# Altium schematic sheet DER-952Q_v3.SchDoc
size A3; Organization: Power Integrations Switzerland GmbH; SheetNumber: 1; SheetTotal: 1; PageSetup: Record=PageOptions¦CenterHorizontal=True¦CenterVertical=True¦PrintScale=1.00¦XCorrection=1.00¦YCorrection=1.00¦PrintKind=0¦BorderSize=5000000¦LeftOffset=0¦BottomOffset=0¦Orientation=2¦PaperLength=4200¦PaperWidth=2970¦Scale=100¦PaperSource=7¦PrintQuality=600¦MediaType=1¦DitherType=10¦PaperKind=A3¦PrintScaleMode=1
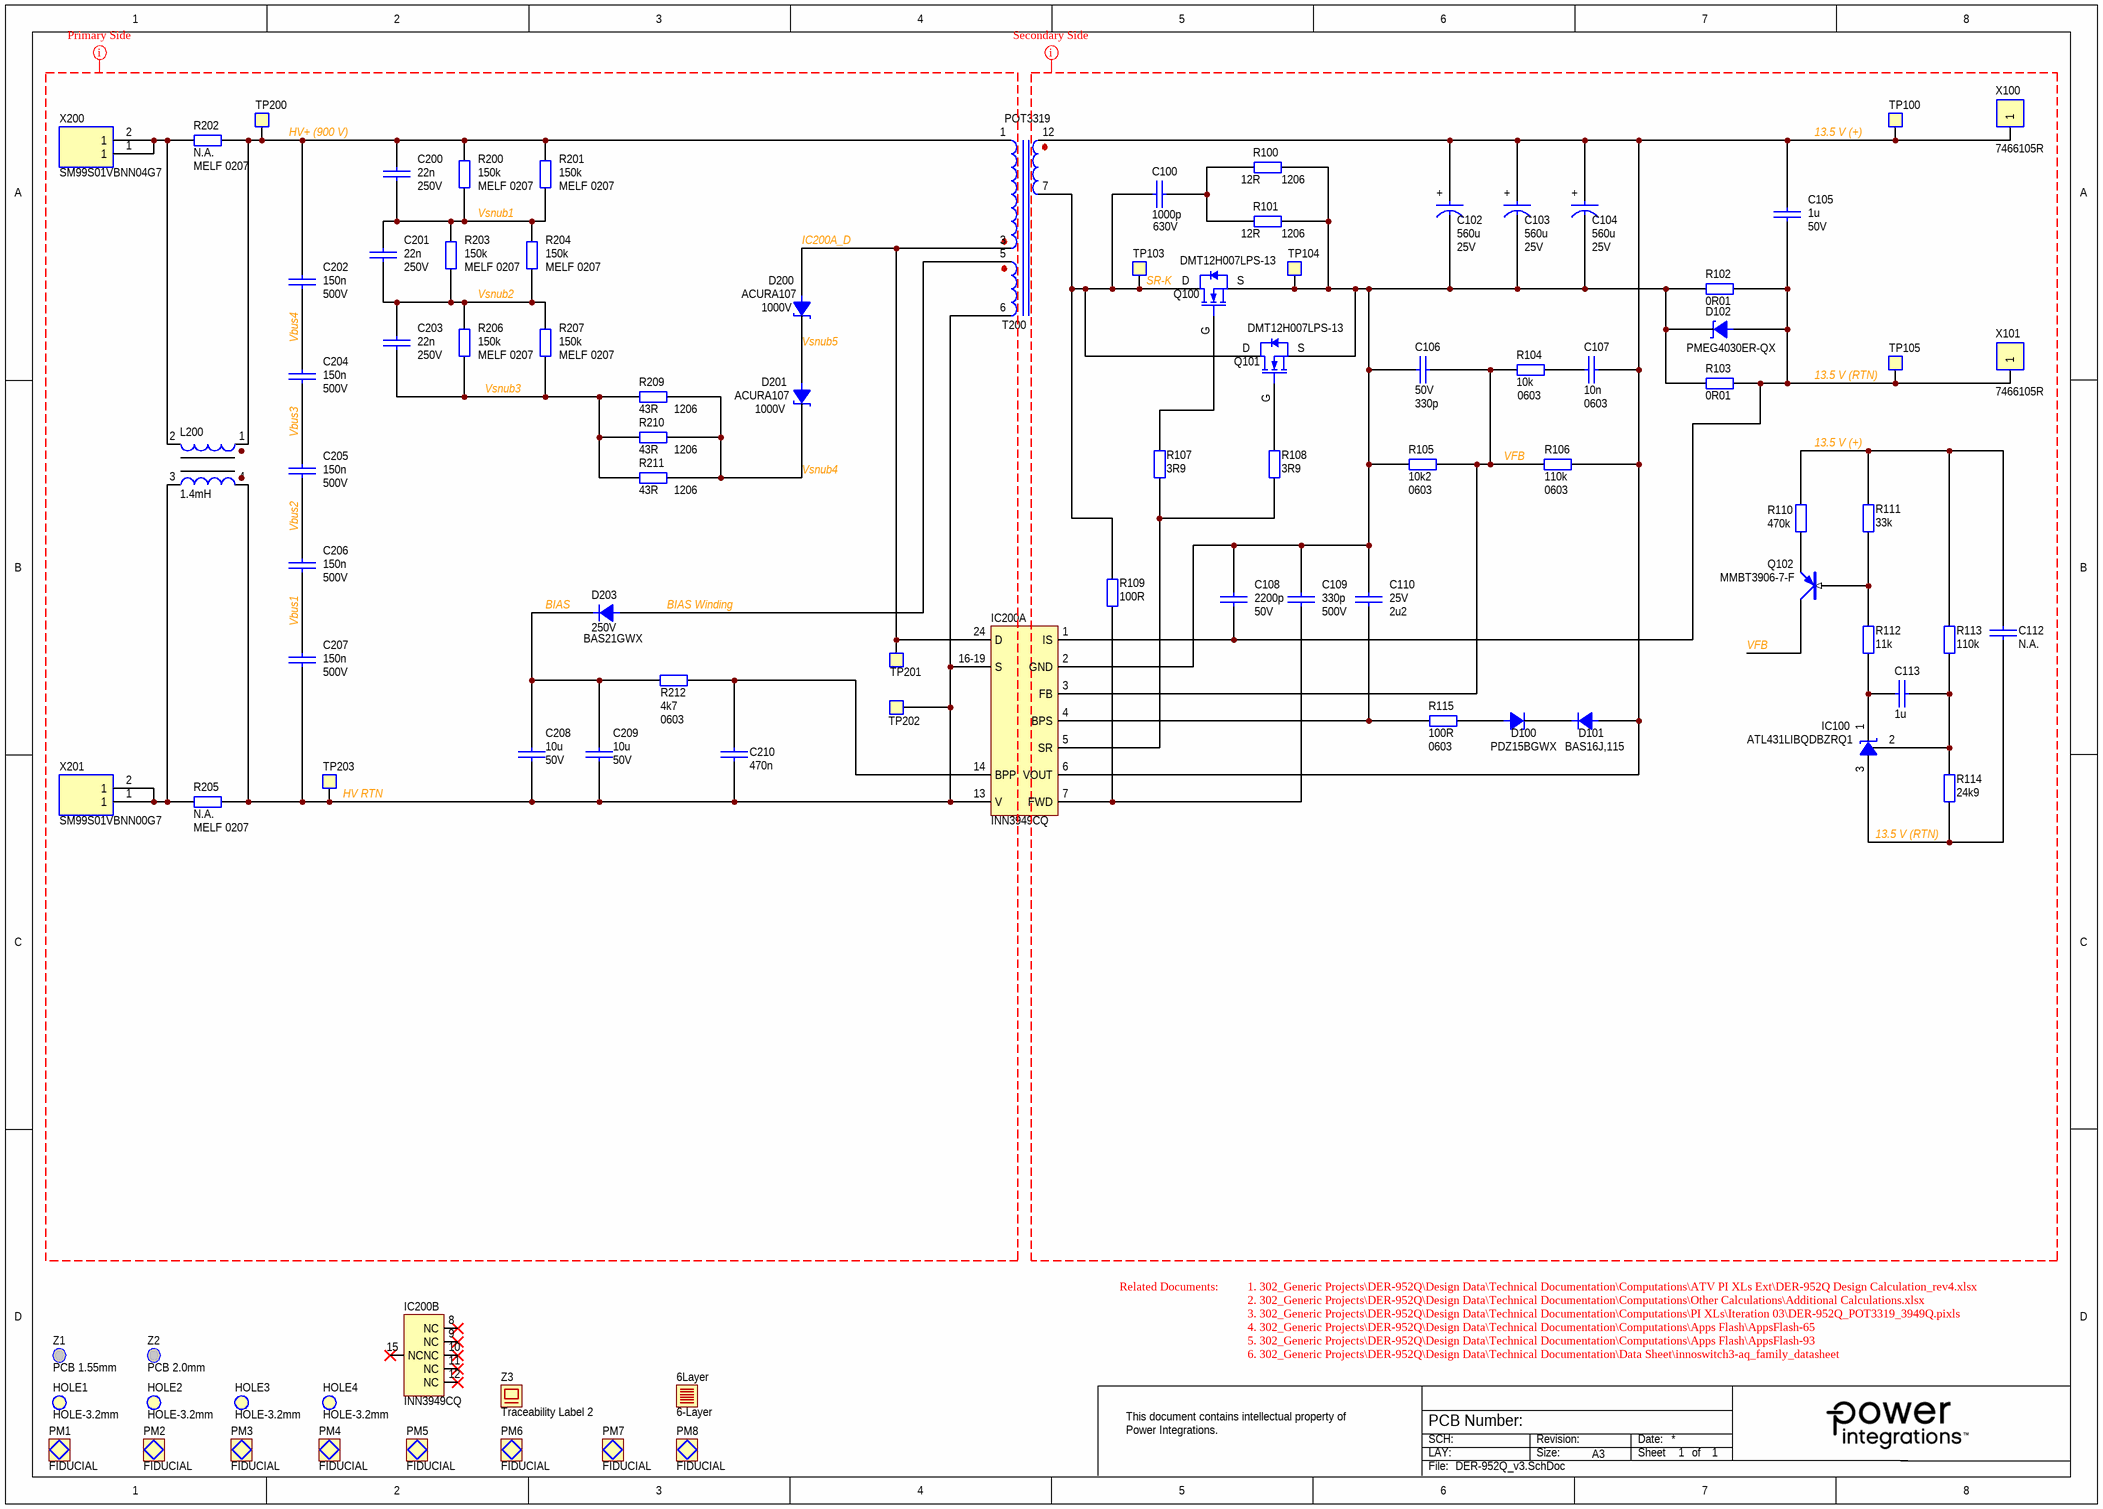
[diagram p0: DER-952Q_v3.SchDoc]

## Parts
6Layer  6-Layer  [PCB_6-LAYER]  (no BOM)
C100  1000p  Voltage: 630V  [ATV_1206_C_RS]
C102  Voltage: 25V  [ATV_CAP_EEH-ZU1E561P]  (hidden comment: 560u)
C103  560u  Voltage: 25V  [ATV_CAP_EEH-ZU1E561P]
C104  Voltage: 25V  [ATV_CAP_EEH-ZU1E561P]  (hidden comment: 560u)
C105  1u  Voltage: 50V  [ATV_1206_C_RS]
C106  Voltage: 50V  [ATV_0603_C_RS]  (hidden comment: 330p)
C107  10n  Package: 0603  [ATV_0603_C_RS]
C108  2200p  Voltage: 50V  [ATV_0603_C_RS]
C109  330p  Voltage: 500V  [ATV_1206_C_RS]
C110  Voltage: 25V  [ATV_1206_C_RS]  (hidden comment: 2u2)
C112  N.A.  [ATV_0603_C_RS]
C113  1u  [ATV_0603_C_RS]
C200  Voltage: 250V  [ATV_1206_C_RS]  (hidden comment: 22n)
C201  Voltage: 250V  [ATV_1206_C_RS]  (hidden comment: 22n)
C202  value 150n  Voltage: 500V  [ATV_1210_C_RS]
C203  Voltage: 250V  [ATV_1206_C_RS]  (hidden comment: 22n)
C204  Voltage: 500V  [ATV_1210_C_RS]  (hidden comment: 150n)
C205  Voltage: 500V  [ATV_1210_C_RS]  (hidden comment: 150n)
C206  Voltage: 500V  [ATV_1210_C_RS]  (hidden comment: 150n)
C207  Voltage: 500V  [ATV_1210_C_RS]  (hidden comment: 150n)
C208  Voltage: 50V  [ATV_1206_C_RS]  (hidden comment: 10u)
C209  Voltage: 50V  [ATV_1206_C_RS]  (hidden comment: 10u)
C210  470n  [ATV_0805_C_RS]
D100  PDZ15BGWX  [ATV_SOD123_RS]
D101  BAS16J,115  [ATV_SOD-323]
D102  PMEG4030ER-QX  [ATV_SOD123_RS]
D200  ACURA107  Reverse Voltage: 1000V  [ATV_DIODE_SMA]
D201  ACURA107  Reverse Voltage: 1000V  [ATV_DIODE_SMA]
D203  value BAS21GWX  Reverse Voltage: 250V  [ATV_SOD123_RS]
HOLE1  HOLE-3.2mm  [PCB_HOLE-3.2_with_standoff]  (no BOM)
HOLE2  HOLE-3.2mm  [PCB_HOLE-3.2_with_standoff]  (no BOM)
HOLE3  HOLE-3.2mm  [PCB_HOLE-3.2_with_standoff]  (no BOM)
HOLE4  HOLE-3.2mm  [PCB_HOLE-3.2_with_standoff]  (no BOM)
IC100  ATL431LIBQDBZRQ1  [CT_SOT23_RS]
IC200  INN3949CQ  [ATV_InSOP-24D]  (parts A,B of 2)
L200  1.4mH  [CT_IND_CMC_FT-3K70T F1613Y_RS]
PM1  FIDUCIAL  [PCB_FIDUCIAL]  (no BOM)
PM2  FIDUCIAL  [PCB_FIDUCIAL]  (no BOM)
PM3  FIDUCIAL  [PCB_FIDUCIAL]  (no BOM)
PM4  FIDUCIAL  [PCB_FIDUCIAL]  (no BOM)
PM5  FIDUCIAL  [PCB_FIDUCIAL]  (no BOM)
PM6  FIDUCIAL  [PCB_FIDUCIAL]  (no BOM)
PM7  FIDUCIAL  [PCB_FIDUCIAL]  (no BOM)
PM8  FIDUCIAL  [PCB_FIDUCIAL]  (no BOM)
Q100  DMT12H007LPS-13  [CT_PowerDI5060-8_RS]
Q101  DMT12H007LPS-13  [CT_PowerDI5060-8_RS]
Q102  MMBT3906-7-F  [CT_SOT23_RS_BIP]
R100  12R  Package: 1206  [ATV_1206_R_RS]
R101  12R  Package: 1206  [ATV_1206_R_RS]
R102  0R01  [ATV_1206_R_RS]
R103  0R01  [ATV_1206_R_RS]
R104  10k  Package: 0603  [ATV_0603_R_RS]
R105  Package: 0603  [ATV_0603_R_RS]  (hidden comment: 10k2)
R106  Package: 0603  [ATV_0603_R_RS]  (hidden comment: 110k)
R107  3R9  [ATV_0805_R_RS]
R108  3R9  [ATV_0805_R_RS]
R109  100R  [ATV_0805_R_RS]
R110  470k  [ATV_0603_R_RS]
R111  33k  [ATV_0603_R_RS]
R112  11k  [ATV_0603_R_RS]
R113  110k  [ATV_0603_R_RS]
R114  24k9  [ATV_0603_R_RS]
R115  Package: 0603  [ATV_0603_R_RS]  (hidden comment: 100R)
R200  150k  Package: MELF 0207  [ATV_MELF_0207]
R201  150k  Package: MELF 0207  [ATV_MELF_0207]
R202  N.A.  Package: MELF 0207  [ATV_MELF_0207]
R203  150k  Package: MELF 0207  [ATV_MELF_0207]
R204  150k  Package: MELF 0207  [ATV_MELF_0207]
R205  N.A.  Package: MELF 0207  [ATV_MELF_0207]
R206  150k  Package: MELF 0207  [ATV_MELF_0207]
R207  150k  Package: MELF 0207  [ATV_MELF_0207]
R209  43R  Package: 1206  [ATV_1206_R_RS]
R210  43R  Package: 1206  [ATV_1206_R_RS]
R211  43R  Package: 1206  [ATV_1206_R_RS]
R212  Package: 0603  [ATV_0603_R_RS]  (hidden comment: 4k7)
T200  value POT3319  [ATV_TRF_POT3319]  (hidden comment: TRF_POT3319)
TP100  ICT-100SP-BL  [ICT-100SP-BL-40MIL]  (value not drawn)  (no BOM)
TP103  ICT-100SP-BL  [ICT-100SP-BL-40MIL]  (value not drawn)  (no BOM)
TP104  ICT-100SP-BL  [ICT-100SP-BL-40MIL]  (value not drawn)  (no BOM)
TP105  ICT-100SP-BL  [ICT-100SP-BL-40MIL]  (value not drawn)  (no BOM)
TP200  ICT-100SP-BL  [ICT-100SP-BL-40MIL]  (value not drawn)  (no BOM)
TP201  ICT-100SP-BL  [ICT-100SP-BL-40MIL]  (value not drawn)  (no BOM)
TP202  ICT-100SP-BL  [ICT-100SP-BL-40MIL]  (value not drawn)  (no BOM)
TP203  ICT-100SP-BL  [ICT-100SP-BL-40MIL]  (value not drawn)  (no BOM)
X100  7466105R  [ATV_CON_7466105R]
X101  7466105R  [ATV_CON_7466105R]
X200  SM99S01VBNN04G7  [ATV_METZ_SM99S01VB]
X201  SM99S01VBNN00G7  [ATV_METZ_SM99S01VB]
Z1  PCB 1.55mm  (mechanical)
Z2  PCB 2.0mm  (mechanical)
Z3  Traceability Label 2  [ATV_TRACEABILITY_LABEL2]  (no BOM)

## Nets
13.5 V (+): C102.1 C103.1 C104.1 C105.1 C107.1 C112.1 D101.A IC200.6(VOUT) R106.2 R110.1 R111.1 R113.1 T200.12(pin7,_pin8) TP100.1 X100.1
13.5 V (RTN): C105.2 C108.2 C112.2 D102.A IC100.3(ANODE) IC200.1(IS) R102.2 R103.2 R114.2 TP105.1 X101.1
BIAS: C208.1 C209.1 D203.K R212.1
BIAS Winding: D203.A T200.5
HV RTN: C207.2 C208.2 C209.2 C210.2 IC200.13(V) IC200.16-19(S) L200.4 R205.2 T200.6 TP202.1 TP203.1
HV+ (900 V): C200.1 C202.1 L200.1 R200.1 R201.1 R202.2 T200.1 TP200.1
IC200A_D: D200.A IC200.24(D) T200.3 TP201.1
SR-K: C100.1 Q100.D(DRAIN) Q101.D(DRAIN) R109.1 T200.7 TP103.1
Vbus1: C206.2 C207.1
Vbus2: C205.2 C206.1
Vbus3: C204.2 C205.1
Vbus4: C202.2 C204.1
VFB: C106.2 IC200.3(FB) Q102.C R104.1 R105.2 R106.1
Vsnub1: C200.2 C201.1 R200.2 R201.2 R203.1 R204.1
Vsnub2: C201.2 C203.1 R203.2 R204.2 R206.1 R207.1
Vsnub3: C203.2 R206.2 R207.2 R209.1 R210.1 R211.1
Vsnub4: D201.K R209.2 R210.2 R211.2
Vsnub5: D200.K D201.A
NetC100_2: C100.2 R100.1 R101.1
NetC102_2: C102.2 C103.2 C104.2 C106.1 C108.1 C109.2 C110.2 D102.K IC200.2(GND) Q100.S(SOURCE) Q101.S(SOURCE) R100.2 R101.2 R102.1 R103.1 R105.1 TP104.1
NetC107_2: C107.2 R104.2
NetC109_1: C109.1 IC200.7(FWD) R109.2
NetC110_1: C110.1 IC200.4(BPS) R115.1
NetC113_1: C113.1 IC100.1(CATHODE) R112.2
NetC113_2: C113.2 IC100.2(REF) R113.2 R114.1
NetC210_1: C210.1 IC200.14(BPP) R212.2
NetD100_A: D100.A R115.2
NetD100_K: D100.K D101.K
NetIC200_5: IC200.5(SR) R107.2 R108.2
NetL200_2: L200.2 R202.1 X200.1 X200.2(1)
NetL200_3: L200.3 R205.1 X201.1 X201.2(1)
NetQ100_G: Q100.G(GATE) R107.1
NetQ101_G: Q101.G(GATE) R108.1
NetQ102_B: Q102.B R111.2 R112.1
NetQ102_E: Q102.E R110.2

Not connected (* = marked no-connect by the designer): IC200 8(NC)* 9(NC)* 10(NC)* 11(NC)* 12(NC)* 15(NC)*

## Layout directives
net class Secondary Side 1: 13.5 V (+), 13.5 V (RTN), SR-K, VFB
net class Primary Side: BIAS, BIAS Winding, HV RTN, HV+ (900 V), IC200A_D, Vbus1, Vbus2, Vbus3, Vbus4, Vsnub1, Vsnub2, Vsnub3, Vsnub4, Vsnub5

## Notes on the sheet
- Input Voltage: 300V to 900V DC
- Reference: #1
  Sheet: Component Selection
  Cell: C143
  ΔV = 5.5% of Vsn
  = .055 * 476.8 V
  = 26.224 V
  I = Vsn / Rsn
  = 476.8 V / 91kOhm
  = 5.23 mA
  Δt = 1/ fs
  = 35.4 us
  Csn = I Δt / ΔV
  = 5.23 mA * 35.4us / 26.224V
  = 7.06 nF
  3 capacitors in series
  Cmin = 7.06nF * 3 = 21.18nF -> 22nF
- Regulated Output:
  Vout = 13.5 V
  Iout = 6.37 A
  Pout = 86 W
- Reference: #1
  Sheet: Component Selection
  Cell: C806
  Reference: #3 PiXls
  Row: 173
- Reference: #1
  Sheet: Component Selection
  Cell: C122
  Lmax = 2458.6uH
  Llk = 1.2% * Lmax
  Ipk = 1.726 A at 28,246 Hz
  Psn = 1/2 * (Llk(Ipk^2)*f) * (Vsn/(Vsn-Vor))
  = 2.5W
  Vsn = 476.8 V
  Rsn = Vsn^2 / Psn
  Rsn = 90.9 kOhm -> 91kOhm
  # of resistors needed
  Resistor Package 1206
  Chosen Rating: 500mW
  Psn,per piece = 2.5W / 9pcs = 278 mW / pc
  *9 pcs, 3x3 resistor array
  278 mW is 55.6% of 500mW
  **Vres,worst case**
  2 resistors at min tolerance, 1 resistor at max tolerance
  tolerance = 5%
  Vres,max = Vsn * (1.05/(1.05 + 2*.95)) = 169 V
  169V is 84.86% of 200V
  **Cooling Area**
  4.5 mm2 per resistor
- (near D201) Reference: #1
  Sheet: Component Selection
  Cell: C160
  Vin,max = 900V
  Vsn = 476.8
  Vpeak = 900 + 476.8 = 1376.8 V
  Vpeak per diode = 1376.8 / 2 = 688.4 V
  688.4 V is 68.8% of 1kV
  maximum reverse recovery time 75ns
  Simulation: Vrms,max per diode is 250V
  Iave = 5.2 mA
  Irms = 77 mA
  Vf,min = .7 V
  Rs = 1.37 ohms
  P = 11 mW
- Reference: #1
  Sheet: Component Selection
  Cell: C793
  Reference: #3 PiXLs
  Row: 172
- (near R106) Reference: #1
  Sheet: Component Selection
  Cell: C778
  Reference: #3 PiXLs
  Row: 171
  Use 100k if precision stage is not used
- Reference: #2
  Sheet: Current Sense
  Cell: C15 C16
  Vsense = 38mV
  Iout = 6.37 A
  Iset = Iout * 1.05
  Iset = 6.68 A
  Rsense = 38mV / 6.68 A = 5.36 mOhms
  Power = 38mV * 6.68 A = 253 mW
  2 x 10 mOhm 1206(250mW each)
- Document: Reference #1
  Sheet: Component Selection
  Cell: C59
  Cin,minimum = 18.6 nF
  Vin,max = 900 V
  Value = 150nF
  Tolerance = 10%
  Quantity in series: 5
  **minimum capacitance based on tolerance**
  Ctotal,minimum = 27 nF > 18.6nF
  **Vcap,worst case**
  4 capacitors at max tolerance, 1 capacitor at minimum tolerance
  Cmin = .9*150nF = 135nF
  Ctotal = 31.59nF
  Vcap,max  = Vs *(Ctotal / Cmin)
  = 900 * (31.59/135)
  = 210V
  Vrated,min = 210 V * 2 = 420 V
  CPG needed at Vcap,max: 2.11mm < 2.2mm
  (1210 package creepage, soft termination)
- Reference: #2
  Sheet: Gate Resistor
  Cell: C24
  Qg = 25 nC at 4.2 V ; per FET
  Qg,total = 50 nC
  Vcc = 4.2 V ; InnoSwitch
  Vgs,th = 2.5 V ; FET
  Rg,inno = 8.5 ohms; internal
  Rg,fet = 1.9 ohms; internal
  Target transition time ->  1% of min period
  t = 330 ns
  Ig = Qg / t
  Rg = (Vcc - Vth) / Ig
  Rg = 11.3 ohms
  Rg' = 11.3 ohms - 8.5 ohms = 2.8 ohms
  Rg'' = 2.8 ohms * 2 = 5.6 ohms ; per branch
  Rg,final = 5.6 ohms - 1.9 ohms = 3.7 ohms ; per branch
- Reference: #1
  Sheet: Component Selection
  Cell: C306
  **DMT12 Specification**
  BVDss = 120 V
  Id = 72 A
  Idm = 360 A
  Vsr,peak = 1.2 * (Vin,Max * Ns / Np + Vout)
  Vsr,peak = 1.2 * (900 * 6/106 ) = 77.3 V
  77.3 V is 64% of 120V
  ATV derating is up to 85%
  Power Loss:
  Irms,sec = 11.83 A ; from PiXL
  Irms = 5.9 A; per FET
  f = 33600 Hz
  Coss, 454pF
  Rds = 14.1 ohm
  Conduction Loss = 493mW
  Switching Loss = 219 mW
  RthJa = 42 degC/W with 645mm^2 copper clad
  Trise = 29.9 degC
- Reference: #1
  Sheet: Component Selection
  Cell: C514
  ****Legend****
  Vesr: ripple voltage due to capacitor ESR
  Vco: rippler voltage due to capacitor value
  Ipk,p: peak current at primary
  Ipk,s: peak current at secondary
  Ipk,r: peak current at output capacitor
  Vr: Vout ripple
  ****Given****
  Vesr / Vco = 1.34; preferred ratio for stability according to apps
  Vr = 35% of 500mV; we chose 35% on of maximum allowed ripple based on specs
  Ipk,p = 1.726 A at 28.2 kHz; from piXL
  Ipk,s = Ipk,p * (Ns/Np) = 1.726 A (106/6)
  Ipk,s = 30.5 A
  Ipk,r = Ipk,s - Iout = 30.5 A - 6.37 A = 24.13 A ; maximum ripple current at capacitor
  ****Derivations****
  (1) Vesr = Ipk,r*(ESR)
  (2) Vco = Ipk,r*/(2*pi*fsw*Co)
  (3) Vr^2 = Vesr^2 + Vco^2
  (4)Vesr / (Vco*ESR) = 2*pi*fsw*Co
  combining eqn 1 up to 4
  (5) Vr^2 = (Ipk,r * ESR)^2 + (Ipk,r*Vco*ESR /  Vesr)^2
  simplifying (5)
  (Vr / Ipk,r)^2 = ESR^2 * [1+ (Vco/Vesr)^2]
  ESR = SQRT[  (Vr / Ipk,r)^2 / [1+ (Vco/Vesr)^2]   ] ; this would be ESR min
  ESRmin =  5.8 mOhms
  use eqn (4) to solve for Co
  Co = [Vesr/(Vco*ESR)] / 2*pi*fsw
  Co = 1.3 mF
  Chosen Capacitor
  3 in parallel
  680uF  20%
  14mOhms
  20V
  4.2Arms ripple
  125degC 4000Hrs
- Reference: #1
  Sheet: Component Selection
  Cell: F742
  Reference: #3 PiXLs
  Row: 164
- Reference: #1
  Sheet: Component Selection
  Cell: F759
  V = Vbias + VinMax*Ns/Np = 11.25 V + 1000*5/106 =  58V
- Reference: #1
  Sheet: Component Selection
  Cell: C165
  Rs = sqrt(Llk / Csn)
  Rs = 63.43 ohms
  closest value 180 ohms, three in parallel to make 60 ohms
  Irms = 77.7 mA
  Prs = Irms^2 * 60ohms = 362 mW
  # of resistors needed
  Resistor Package 1206
  Chosen Rating 250mW
  Pres, per piece = 362mW / 3 = 120mW
  120mW is 48% of 250mW
- Reference: #5
  Page 5
  330p
  Vmax = 1.2 * (Vin,Max * Ns / Np + Vout)
  Vmax = 77.3 V
  Vrating = 77.3V *2 = 155V
  package 1206
- Reference: #6
  Page 9
  2u2 is recommended for BPS capacitor
  Vbps = 4.6V
  Vrating > 4.6 V * 2 = 9.2V
  1206 was chosen for layout purposes, so that Vfb node can pass in between
- Reference: #1
  Sheet: Component Selection
  Cell: F737
  Reference: #3 PiXLs
  Row: 165
  4.7uF needed for increased Ilimit
  Vbpp,clamp*2 = 5.65*2 = 11.3V -> choose next higher 16V
  0805 since there is no 4.7uF 16V in 0603
- Reference: #4
  Page 3
  R = 100ohms
  f = 28 kHz
  C = 330 pF
  Vmax = 1.2 * (Vin,Max * Ns / Np + Vout)
  Vmax = 77.3 V
  P =  f*C*V^2
  P = 55mW
  R should be:
  100 ohms
  125mW
  0805
- working value during preliminary test
- Reference: #1
  Sheet: Component Selection
  Cell: C712
  Vb,nl: V bias at no load
  Vbpp: 5.65 V maximum shunt voltage
  Nb: turns bias
  Ns: turns secondary
  fsw,max = 37kHz
  Issw = fsw/132khz * (Is2 - Is1) + Is1 ; Inno3 family design guide pg 18
  Issw = 37k / 132k * (3000uA - 489uA) + 489uA
  Issw = 1192 uA
  Vb,nl = Vout*Nb/Ns
  Vb,nl = 13.5V*5/6
  Vb,nl = 11.25 V
  Rbp = (Vb,nl - Vbpp) / Issw
  Rbp = (11.25 - 5.65)V / 1192uA
  Rbp = 4697 ohms ; choose 4.7 kOhms
- Vout = 13.5 V
  Ibps,sd = 12mA ; current needed for secondary OVP
  Vbps = 4.4V
  Vovp = Vout * 1.25
  Vovp = 13.5 V * 1.25 = 16.87 V
  Vdrop = Vovp - Vbps
  Vdrop = 16.87V - 4.4 V = 12.47 V
  Vdrop = Vz + Vf
  BAS16J standard diode
  Vf = 0.7 V  at 10mA
  Vz = 12.47 V - 0.7 V = 11.77 V  12V
  BZT52C12
- Reference: #1
  Sheet: Component Selection
  Cell: C262
  Vin,max = 900V
  Vsn = 476.8
  Vpeak = 900 + 476.8 = 1376.8 V
  BVds,Inno = 1700 V
  1376.8 V is 80% of 1700 V
  ATV rule is 85%
  Simulation: Vds,rms = 977 V
  CPG,req = 4.9 mm
  D-S,inno = 3.35mm 'place a slot in layout'
  Power Loss:
  PiXL setpoint analysis
  At Vin = 300 V
  Irms = 0.574 A
  f = 33600 Hz
  Coss, 9pF
  Rds = 1.1 ohm
  Conduction Loss = 362mW
  Switching Loss = 27 mW
  RthJa = 70 degC/W with 645mm^2 copper clad
  Trise = 27 degC
- Related Documents:
- 1. 302_Generic Projects\DER-952Q\Design Data\Technical Documentation\Computations\ATV PI XLs Ext\DER-952Q Design Calculation_rev4.xlsx
- 2. 302_Generic Projects\DER-952Q\Design Data\Technical Documentation\Computations\Other Calculations\Additional Calculations.xlsx
- 3. 302_Generic Projects\DER-952Q\Design Data\Technical Documentation\Computations\PI XLs\Iteration 03\DER-952Q_POT3319_3949Q.pixls
- 4. 302_Generic Projects\DER-952Q\Design Data\Technical Documentation\Computations\Apps Flash\AppsFlash-65
- 5. 302_Generic Projects\DER-952Q\Design Data\Technical Documentation\Computations\Apps Flash\AppsFlash-93
- 6. 302_Generic Projects\DER-952Q\Design Data\Technical Documentation\Data Sheet\innoswitch3-aq_family_datasheet

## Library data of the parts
6Layer = ATV-MISC-0011: Second Source: N; Release Status: active; Release Status Sign: GW
C100 = ATV-CAP-0396: Part Description: Ceramic Chip Capacitor; Manufacturer 1: TDK Corporation; Parameters: C0G/630V/5%; Dielectric: NP0,C0G; Tolerance: 5%; Second Source: N; AEC-Q: AEC-Q200; Target Usage: for product use; Type Designation 1: CGA5F4C0G2J102J085AA; Confidence Level: 0%; Release Status: inactive; Release Status Sign: RAA
C102 C104 = ATV-CAP-0337: Part Description: Polymer Aluminium Capacitor; Manufacturer 1: Panasonic Electronic Components; Parameters: AL/25V/20%; Tolerance: 20%; Second Source: Y; Target Usage: for product use; Confidence Level: 0%; Release Status: inactive; Release Status Sign: RAA; Dielectric: AL; Type Designation 1: EEH-ZU1E561P; AEC-Q: AEC-Q200
C103 = ATV-CAP-0337: Part Description: Polymer Aluminium Capacitor; Manufacturer 1: Panasonic Electronic Components; Target Usage: for product use; Confidence Level: 0%; Release Status: inactive; Release Status Sign: RAA; Parameters: AL/25V/20%; Dielectric: AL; Tolerance: 20%; Second Source: Y; Type Designation 1: EEH-ZU1E561P; AEC-Q: AEC-Q200
C105 = ATV-CAP-0418: Part Description: Ceramic Chip Capacitor; Manufacturer 1: TDK Corporation; Parameters: X7R/50V/10%; Dielectric: X7R; Tolerance: 10%; Second Source: N; AEC-Q: AEC-Q200; Target Usage: for product use; Type Designation 1: CGA5L3X7R1H105K160AE; Confidence Level: 0%; Release Status: inactive; Release Status Sign: RAA
C106 = ATV-CAP-0354: Part Description: Ceramic Chip Capacitor; Manufacturer 1: TDK Corporation; Parameters: C0G/50V/5%; Dielectric: C0G; Tolerance: 5%; Second Source: Y; AEC-Q: AEC-Q200; Target Usage: for product use; Confidence Level: 0%; Release Status: inactive; Release Status Sign: RAA; Type Designation 1: CGA3E2C0G1H331J080AA
C107 = ATV-CAP-0263: Part Description: Ceramic Chip Capacitor; Manufacturer 1: KEMET; Parameters: X7R/50V/10%; Dielectric: X7R; Voltage: 50V; Tolerance: 10%; Second Source: Y; AEC-Q: AEC-Q200; Target Usage: for product use; Type Designation 1: C0603C103K5RACAUTO7411; Confidence Level: 0%; Release Status: inactive; Release Status Sign: RAA
C108 = ATV-CAP-0417: Part Description: Ceramic Chip Capacitor; Manufacturer 1: Murata Electronics; Parameters: C0G/50V/5%; Dielectric: NP0,C0G; Tolerance: 5%; Second Source: N; AEC-Q: AEC-Q200; Target Usage: for product use; Type Designation 1: GCM1885C1H222JA16D; Confidence Level: 0%; Release Status: inactive; Release Status Sign: RAA
C109 = ATV-CAP-0312: Part Description: Ceramic Chip Capacitor; Manufacturer 1: KEMET; Parameters: C0G/500V/10%; Dielectric: C0G; Tolerance: 10%; Second Source: Y; AEC-Q: AEC-Q200; Target Usage: for product use; Confidence Level: 0%; Release Status: inactive; Release Status Sign: RAA; Type Designation 1: C1206C331KCGACAUTO
C110 = ATV-CAP-0355: Part Description: Ceramic Chip Capacitor; Manufacturer 1: TDK Corporation; Parameters: X7R/25V/20%; Dielectric: X7R; Tolerance: 20%; Second Source: Y; AEC-Q: AEC-Q200; Target Usage: for product use; Confidence Level: 0%; Release Status: inactive; Release Status Sign: RAA; Type Designation 1: CGA5L2X7R1E225M160AA
C112 = ATV-CAP-0296: Part Description: Ceramic Chip Capacitor; Confidence Level: 0%; Release Status: inactive; Release Status Sign: RAA
C113 = ATV-CAP-0358: Part Description: Ceramic Chip Capacitor; Manufacturer 1: TDK Corporation; Parameters: X7R/25V/20%; Confidence Level: 0%; Release Status: inactive; Release Status Sign: RAA; Dielectric: X7R; Voltage: 25V; Tolerance: 20%; Second Source: Y; AEC-Q: AEC-Q200; Target Usage: for product use; Type Designation 1: CGA3E1X7R1E105M080AC
C200 C201 C203 = ATV-CAP-0352: Part Description: Ceramic Chip Capacitor; Manufacturer 1: Murata; Parameters: X7R/250V/10%; Dielectric: X7R; Tolerance: 10%; Second Source: Y; AEC-Q: AEC-Q200; Target Usage: for product use; Confidence Level: 0%; Release Status: inactive; Release Status Sign: RAA; Type Designation 1: GCJ31BR72E223KXJ1L
C202 C204-C207 = ATV-CAP-0309: Part Description: Ceramic Chip Capacitor; Manufacturer 1: KEMET; Parameters: X7R/500V/10%; Dielectric: X7R; Tolerance: 10%; Second Source: Y; AEC-Q: AEC-Q200; Target Usage: for product use; Confidence Level: 0%; Release Status: inactive; Release Status Sign: RAA; Type Designation 1: C1210X154KCRACAUTO
C208 C209 = ATV-CAP-0266: Part Description: Ceramic Chip Capacitor; Manufacturer 1: TDK; Parameters: X7R/50V/10%; Dielectric: X7R; Tolerance: 10%; Second Source: Y; AEC-Q: AEC-Q200; Target Usage: for product use; Confidence Level: 0%; Release Status: inactive; Release Status Sign: RAA; Type Designation 1: CGA5L1X7R1H106K160AC
C210 = ATV-CAP-0264: Part Description: Ceramic Chip Capacitor; Manufacturer 1: YAGEO; Parameters: X7R/16V/10%; Dielectric: X7R; Voltage: 16V; Tolerance: 10%; Second Source: Y; AEC-Q: AEC-Q200; Target Usage: for product use; Type Designation 1: AC0805KKX7R7BB474; Confidence Level: 0%; Release Status: active; Release Status Sign: RAA
D100 = ATV-DIO-0117: Part Description: Zener Diode 15 V 365 mW; Manufacturer 1: Nexperia USA Inc.; Parameters: 15V; AEC-Q: AEC-Q101; Target Usage: for product use; Confidence Level: 0%; Release Status: inactive; Release Status Sign: RAA; Forward Voltage: 1.1 V @ 100 mA; Current: 50 nA @ 11 V; Power: 365mW; Tolerance: 2.13%; Second Source: N
D101 = ATV-DIO-0104: Part Description: Diode Standard 100 V 250mA; Manufacturer 1: Nexperia; Parameters: 100V; Forward Voltage: 1.25 V @ 150 mA; Current: 500 nA @ 80 V; Target Usage: for product use; Confidence Level: 0%; Release Status: inactive; Release Status Sign: RAA; Second Source: N; AEC-Q: AEC-Q101
D102 = ATV-DIO-0146: Part Description: Schottky Diode; Manufacturer 1: Nexperia; Parameters: 40V/3A; AEC-Q: AEC-Q101; Target Usage: for product use; Confidence Level: 0%; Release Status: inactive; Release Status Sign: RAA; Forward Voltage: 540 mV @ 3 A; Current: 100 µA @ 40 V; Second Source: N; Voltage: 40V
D200 D201 = ATV-DIO-0072: Part Description: DIODE SCHOTTKY 1KV 1A; Manufacturer 1: Comchip Technology; Parameters: 1000V / 1A; Forward Voltage: 1.7 V @ 1 A; Current: 1A; Target Usage: for product use; Confidence Level: 0%; Release Status: inactive; Release Status Sign: RAA; Second Source: N; Type Designation 1: ACURA107-HF; AEC-Q: AEC-Q101
D203 = ATV-DIO-0036: Part Description: Diode Standard 200 V 225mA (DC) Surface Mount SOD-123; Manufacturer 1: Nexperia; Parameters: 200 V / 225mA; Forward Voltage: 1.25v @ If = 200mA; Current: 200mA; AEC-Q: AEC-Q101; Target Usage: for product use; Confidence Level: 0%; Release Status: inactive; Release Status Sign: RAA; Power: 250mW; Second Source: N
HOLE1-HOLE4 = ATV-MISC-0013: Part Description: 3.2mm; Second Source: N; Release Status: active; Release Status Sign: GW
IC100 = ATV-IC-0058: Part Description: Voltage References Automotive, high-bandwidth, low-IQ programmable shunt regulator; Manufacturer 1: Texas Instruments; Parameters: 2.5 V to 36 V; Output Current: 15mA; Second Source: N; AEC-Q: AEC-Q100; Target Usage: for product use; Confidence Level: 0%; Release Status: inactive; Release Status Sign: RAA
IC200 = ATV-IC-0054: Part Description: InnoSwitch3; Manufacturer 1: Power Integrations; Parameters: 4.65V to 5.15V/Vmos=1700V; Supply Voltage: 4.65V to 5.15V; Other: Ilim=2.3A, Pout=60W; Second Source: N; AEC-Q: AEC-Q100; Target Usage: for product use; Confidence Level: 0%; Release Status: inactive; Release Status Sign: RAA
L200 = ATV-IND-0016: Part Description: Input Common Mode Choke; Manufacturer 1: Coilcraft; Current: 2.5A; Resistor: 60mOhm; Second Source: N; AEC-Q: AEC-Q200; Target Usage: for product use; Type Designation 1: CM6518-AL; Confidence Level: 0%; Release Status: active; Release Status Sign: RAA
PM1-PM8 = ATV-MISC-0007: Part Description: Mark; Second Source: N; Release Status: active; Release Status Sign: GW
Q100 Q101 = ATV-FET-0039: Part Description: N-Channel MOSFET; Manufacturer 1: Diodes; Target Usage: for product use; Confidence Level: 0%; Release Status: inactive; Release Status Sign: RAA; Parameters: 120 V 90A (Ta), 90A (Tc) 2.9W (Ta); Gates: 1; Polarisation: N; Voltage: 120V; Current: 90A; Power: 2.9W; Resistor: 7.8mOhm @ Vgs = 10V / Id = 30; AEC-Q: AEC-Q101
Q102 = ATV-BIP-0012: Part Description: 40V/0.2A PNP bipolar transistor; Manufacturer 1: Diodes; Parameters: PNP/40V/0.2A/300mW; Polarisation: PNP; Voltage: 40V; Current: 0.2A; Power: 300mW; Second Source: N; Target Usage: for product use; Confidence Level: 0%; Release Status: inactive; Release Status Sign: RAA; AEC-Q: AEC-Q101
R100 R101 = ATV-RES-0824: Part Description: Thick Film Chip Resistor; Manufacturer 1: YAGEO; Parameters: 5%/0.25W/200V; Tolerance: 5%; Power: 0.25W; Second Source: Y; AEC-Q: AEC-Q200; Target Usage: for product use; Type Designation 1: AC1206JR-0712RL; Confidence Level: 0%; Release Status: inactive; Release Status Sign: RAA
R102 R103 = ATV-RES-1073: Part Description: Current Sense Resistor; Manufacturer 1: Vishay Dale; Parameters: 0.5%/0.25W/200V; Tolerance: 0.5%; Power: 0.25W; Voltage: 200V; Second Source: Y; AEC-Q: AEC-Q200; Target Usage: for product use; Type Designation 1: WSL1206R0100DEA; Confidence Level: 0%; Release Status: inactive; Release Status Sign: RAA
R104 = ATV-RES-0827: Part Description: Thick Film Chip Resistor; Manufacturer 1: YAGEO; Parameters: 5%/0.1W/75V; Tolerance: 5%; Power: 0.1W; Second Source: Y; AEC-Q: AEC-Q200; Target Usage: for product use; Type Designation 1: AC0603JR-0710KL; Confidence Level: 0%; Release Status: inactive; Release Status Sign: RAA
R105 = ATV-RES-0938: Part Description: Thick Film Chip Resistor; Manufacturer 1: Stackpole Electronics Inc; Power: 0.1W; Tolerance: 1%; AEC-Q: AEC-Q200; Target Usage: for product use; Confidence Level: 0%; Release Status: inactive; Release Status Sign: RAA; Parameters: 1%/0.1W/150V; Second Source: Y; Type Designation 1: RMCF0603FT10K2
R106 = ATV-RES-0946: Part Description: Thick Film Chip Resistor; Manufacturer 1: Stackpole Electronics Inc; Power: 0.1W; Tolerance: 5%; AEC-Q: AEC-Q200; Target Usage: for product use; Confidence Level: 0%; Release Status: inactive; Release Status Sign: RAA; Parameters: 5%/0.1W/150V; Second Source: Y; Type Designation 1: RMCF0603JT110K
R107 R108 = ATV-RES-0936: Part Description: Thick Film Chip Resistor; Manufacturer 1: Stackpole Electronics Inc; Parameters: 5%/0.125W/150V; Tolerance: 5%; Power: 0.125W; Second Source: Y; AEC-Q: AEC-Q200; Target Usage: for product use; Type Designation 1: RMCF0805JT3R90; Confidence Level: 0%; Release Status: inactive; Release Status Sign: RAA
R109 = ATV-RES-0939: Part Description: Thick Film Chip Resistor; Manufacturer 1: Stackpole Electronics Inc; Parameters: 5%/0.125W/150V; Tolerance: 5%; Power: 0.125W; Second Source: Y; AEC-Q: AEC-Q200; Target Usage: for product use; Type Designation 1: RMCF0805JT100R; Confidence Level: 0%; Release Status: inactive; Release Status Sign: RAA
R110 = ATV-RES-0944: Part Description: Thick Film Chip Resistor; Manufacturer 1: Stackpole Electronics Inc; Confidence Level: 0%; Release Status: inactive; Release Status Sign: RAA; Parameters: 5%/0.1W/150V; Tolerance: 5%; Power: 0.1W; Second Source: Y; AEC-Q: AEC-Q200; Target Usage: for product use; Type Designation 1: RMCF0603JT470K
R111 = ATV-RES-0945: Part Description: Thick Film Chip Resistor; Manufacturer 1: Stackpole Electronics Inc; Confidence Level: 0%; Release Status: inactive; Release Status Sign: RAA; Parameters: 5%/0.1W/150V; Tolerance: 5%; Power: 0.1W; Second Source: Y; AEC-Q: AEC-Q200; Target Usage: for product use; Type Designation 1: RMCF0603JT33K0
R112 = ATV-RES-0947: Part Description: Thick Film Chip Resistor; Manufacturer 1: Stackpole Electronics Inc; Confidence Level: 0%; Release Status: inactive; Release Status Sign: RAA; Parameters: 5%/0.1W/150V; Tolerance: 5%; Power: 0.1W; Second Source: Y; AEC-Q: AEC-Q200; Target Usage: for product use; Type Designation 1: RMCF0603JT11K0
R113 = ATV-RES-0943: Part Description: Thick Film Chip Resistor; Manufacturer 1: Stackpole Electronics Inc; Confidence Level: 0%; Release Status: inactive; Release Status Sign: RAA; Parameters: 1%/0.1W/150V; Tolerance: 1%; Power: 0.1W; Second Source: Y; AEC-Q: AEC-Q200; Target Usage: for product use; Type Designation 1: RMCF0603FT110K
R114 = ATV-RES-0942: Part Description: Thick Film Chip Resistor; Manufacturer 1: Stackpole Electronics Inc; Confidence Level: 0%; Release Status: inactive; Release Status Sign: RAA; Parameters: 1%/0.1W/150V; Tolerance: 1%; Power: 0.1W; Second Source: Y; AEC-Q: AEC-Q200; Target Usage: for product use; Type Designation 1: RMCF0603FT24K9
R115 = ATV-RES-0753: Part Description: Thick Film Chip Resistor; Manufacturer 1: Stackpole Electronics Inc; Power: 0.1W; Tolerance: 5%; AEC-Q: AEC-Q200; Target Usage: for product use; Confidence Level: 0%; Release Status: inactive; Release Status Sign: RAA; Parameters: 5%/0.1W; Second Source: Y; Type Designation 1: RMCF0603JT100R
R200 R201 R203 R204 R206 R207 = ATV-RES-0979: Part Description: MELF Resistors; Manufacturer 1: Vishay / Beyschlag; Power: 1W; Tolerance: 2%; AEC-Q: AEC-Q200; Target Usage: for product use; Confidence Level: 0%; Release Status: inactive; Release Status Sign: RAA; Parameters: 2%/1W/200V; Second Source: N; Type Designation 1: CMB02070X1503GB200; Voltage: 200V
R202 R205 = ATV-RES-1026: Part Description: MELF Resistors; Power: 1W; Tolerance: 1%; AEC-Q: AEC-Q200; Target Usage: for product use; Confidence Level: 0%; Release Status: inactive; Release Status Sign: RAA; Parameters: 1%/1W/200V; Second Source: N; Voltage: 200V
R209-R211 = ATV-RES-0750: Part Description: Thick Film Chip Resistor; Manufacturer 1: Stackpole Electronics Inc; Parameters: 5%/0.25W; Tolerance: 5%; Power: 0.25W; Second Source: Y; AEC-Q: AEC-Q200; Target Usage: for product use; Type Designation 1: RMCF1206JT43R0; Confidence Level: 0%; Release Status: inactive; Release Status Sign: RAA
R212 = ATV-RES-0937: Part Description: Thick Film Chip Resistor; Manufacturer 1: Stackpole Electronics Inc; Power: 0.1W; Tolerance: 5%; AEC-Q: AEC-Q200; Target Usage: for product use; Confidence Level: 0%; Release Status: inactive; Release Status Sign: RAA; Parameters: 5%/0.1W/150V; Second Source: Y; Type Designation 1: RMCF0603JT4K70
T200 = ATV-TRF-0031: Part Description: Selfmade Transformer on base POT3319; Manufacturer 1: Power Integrations; Second Source: N; Target Usage: for product use; Confidence Level: 0%; Release Status: inactive; Release Status Sign: RAA
TP100 TP103-TP105 TP200-TP203 = ATV-MISC-0002: Part Description: Spring Probes 2.54mm; Manufacturer 1: UWE electronic; Second Source: N; Type Designation 1: ICT100SPB6.7GS-RX100WW; Confidence Level: 0%; Release Status: active; Release Status Sign: GW
X100 X101 = ATV-CON-0090: Part Description: 1 Pin Screw Terminal, Power Tap M5 Surface Mount; Manufacturer 1: Würth Elektronik; Parameters: 70A; Target Usage: for product use; Confidence Level: 0%; Release Status: inactive; Release Status Sign: RAA
X200 = ATV-MISC-0037: Part Description: TERM BLOCK 1POS SIDE ENTRY SMD; Manufacturer 1: METZ CONNECT USA Inc.; Parameters: RED; Second Source: N; Target Usage: for product use; Confidence Level: 0%; Release Status: active; Release Status Sign: RAA
X201 = ATV-MISC-0036: Part Description: TERM BLOCK 1POS SIDE ENTRY SMD; Manufacturer 1: METZ CONNECT USA Inc.; Parameters: BLACK; Second Source: N; Target Usage: for product use; Confidence Level: 0%; Release Status: active; Release Status Sign: RAA
Z1 = ATV-MISC-0005: Part Description: Printed Circuit Board; Parameters: PCB thickness 1.55mm; Second Source: N; Release Status: active; Release Status Sign: GW
Z2 = ATV-MISC-0001: Part Description: Printed Circuit Board; Parameters: PCB thickness 2.0mm; Second Source: N; Release Status: active; Release Status Sign: GW
Z3 = ATV-LABEL-0016: Part Description: Label 8 x 8mm; Manufacturer 1: power integrations; Second Source: N; Confidence Level: 0%; Release Status: inactive; Release Status Sign: RAA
